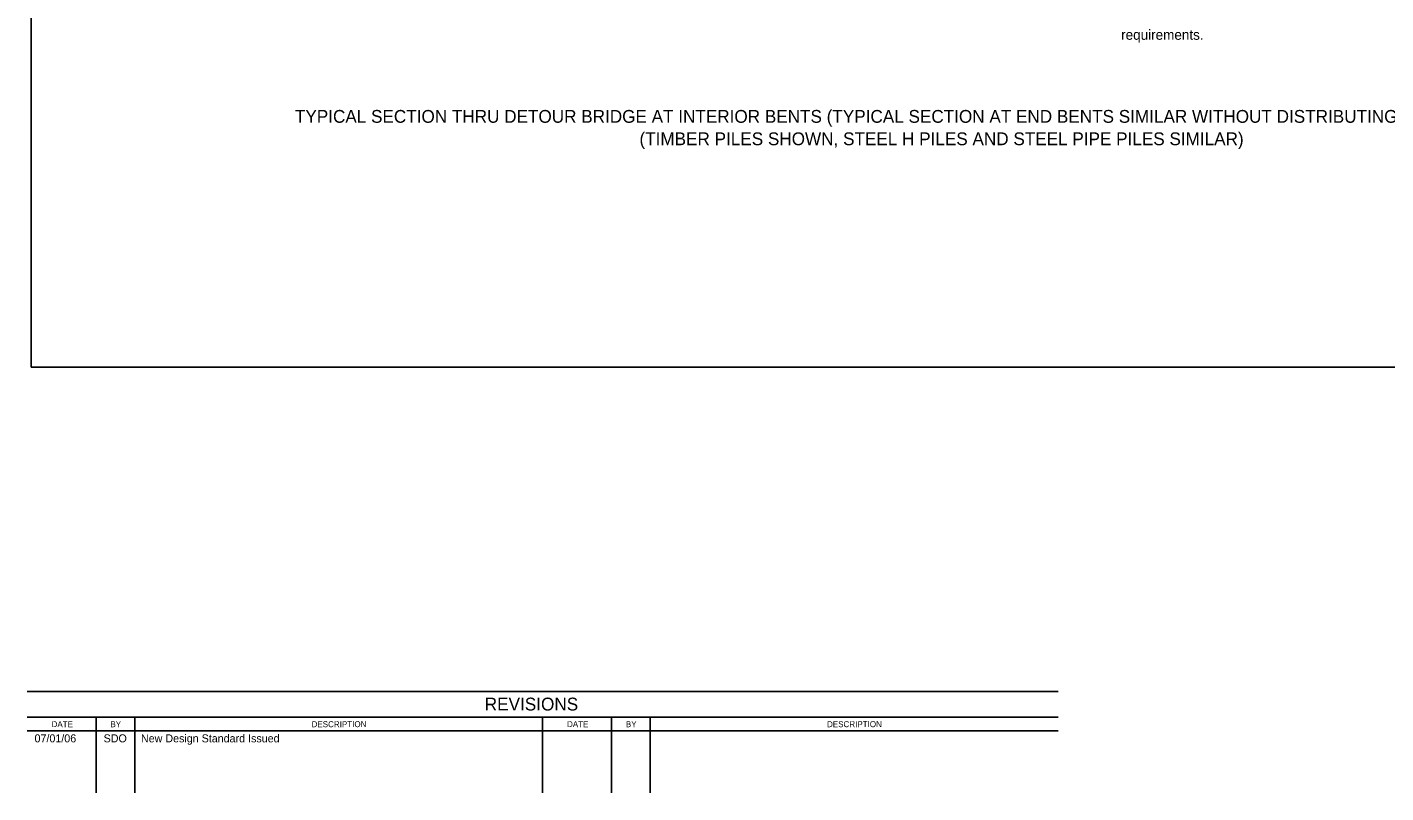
# Model space of a CAD drawing. Extents: x 11137.4 to 11208.2, y 76297.7 to 76332.4.
# Drawn here: x 11137.36 to 11164.53, y 76297.7 to 76313.02 of the extents above; entities that cross this region are included whole.
import ezdxf

# ---------------------------------------------------------------- set-up
doc = ezdxf.new("R2010")
doc.units = 0
for name, color, linetype in [('ActivePts-ConstElements', 7, 'Continuous'), ('Border', 7, 'Continuous'), ('TextStructures', 7, 'Continuous')]:
    doc.layers.add(name, color=color, linetype=linetype)

msp = doc.modelspace()

# ---------------------------------------------------------------- linework, layer by layer
at = {"layer": 'ActivePts-ConstElements'}
msp.add_lwpolyline([(11137.439, 76306.213), (11178.49, 76306.213), (11178.49, 76332.159), (11137.439, 76332.159)], close=True, dxfattribs=at)
at = {"layer": 'Border'}
for p, q in [((11157.973, 76299.733), (11137.362, 76299.733)), ((11157.973, 76299.218), (11137.362, 76299.218)), ((11138.738, 76299.218), (11138.738, 76297.703)), ((11139.512, 76299.218), (11139.512, 76297.703)), ((11147.668, 76299.218), (11147.668, 76297.703)), ((11149.044, 76299.218), (11149.044, 76297.703)), ((11149.818, 76299.218), (11149.818, 76297.703)), ((11137.362, 76298.945), (11157.973, 76298.945))]:
    msp.add_line(p, q, dxfattribs=at)

# ---------------------------------------------------------------- texts
at = {"layer": 'TextStructures'}
for s, height, p in [('requirements.', 0.2016, (11159.235, 76312.763)), ('TYPICAL SECTION THRU DETOUR BRIDGE AT INTERIOR BENTS (TYPICAL SECTION AT END BENTS SIMILAR WITHOUT DISTRIBUTING BEAMS)', 0.256001, (11142.715, 76311.103)), ('(TIMBER PILES SHOWN, STEEL H PILES AND STEEL PIPE PILES SIMILAR)', 0.256, (11149.604, 76310.655)), ('REVISIONS', 0.2567, (11146.51, 76299.35)), ('BY', 0.1201, (11139.026, 76299.016)), ('BY', 0.1201, (11149.332, 76299.016)), ('07/01/06', 0.16, (11137.509, 76298.713)), ('SDO', 0.16, (11138.89, 76298.713)), ('New Design Standard Issued', 0.16, (11139.637, 76298.713))]:
    msp.add_text(s, height=height, dxfattribs=at).set_placement(p)
for s, height, rotation, p in [('DATE', 0.1196, 359.8693, (11137.85, 76299.017)), ('DESCRIPTION', 0.12007, 0.0498, (11143.048, 76299.016)), ('DATE', 0.1196, 359.8693, (11148.156, 76299.017)), ('DESCRIPTION', 0.12007, 0.0498, (11153.354, 76299.016))]:
    msp.add_text(s, height=height, rotation=rotation, dxfattribs=at).set_placement(p)

doc.saveas('drawing.dxf')
